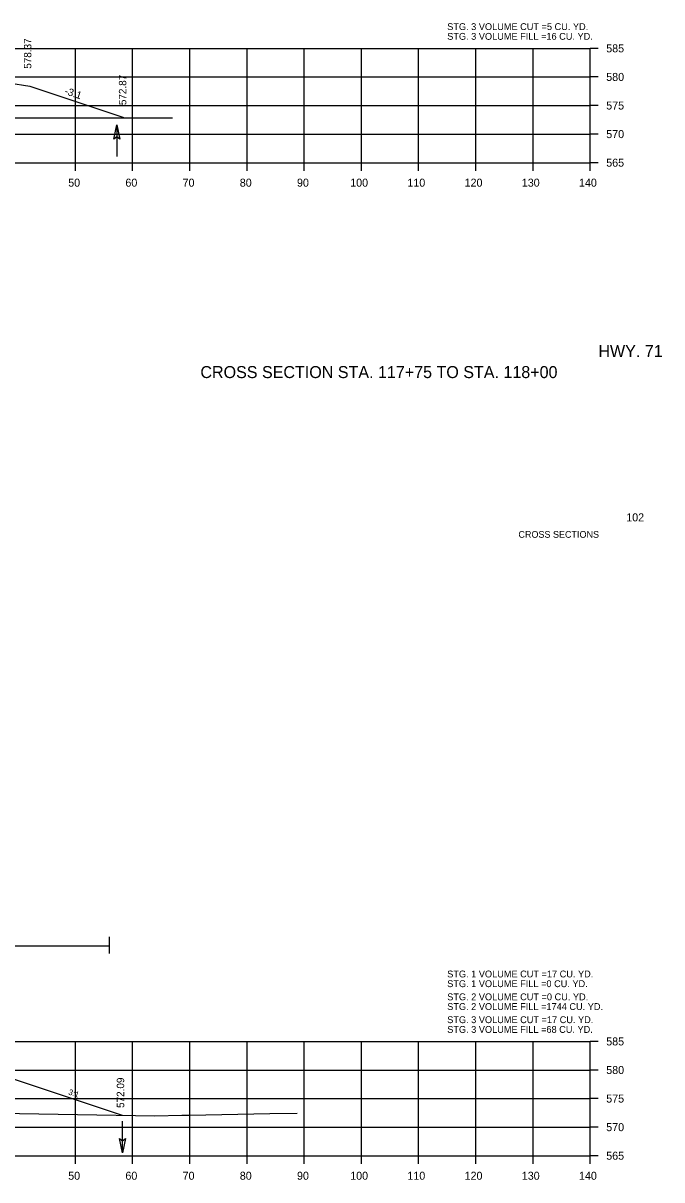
# Model space of a CAD drawing. Extents: x 642114 to 642416, y 286928 to 293347.
# Drawn here: x 642301.1 to 642412.8, y 290342.3 to 290544.7 of the extents above; entities that cross this region are included whole.
import ezdxf

# ---------------------------------------------------------------- set-up
doc = ezdxf.new("R2010")
doc.units = 0
for name, color, linetype in [('Level 43', 7, 'Continuous'), ('Level 58', 7, 'Continuous'), ('R_Axis', 7, 'Continuous'), ('R_Axis Annot', 7, 'Continuous'), ('R_Border', 7, 'Continuous'), ('R_Border Notes', 7, 'Continuous'), ('R_Draft', 7, 'Continuous'), ('R_Exist Surface Annot', 7, 'Continuous'), ('R_Fin Surface', 7, 'Continuous'), ('R_Grid', 7, 'Continuous'), ('R_Xsect Elev', 7, 'Continuous'), ('R_Xsect Slope', 7, 'Continuous')]:
    doc.layers.add(name, color=color, linetype=linetype)

# ---------------------------------------------------------------- blocks, each defined once
blk = doc.blocks.new('FA')
at = {"layer": 'Level 43'}
blk.add_lwpolyline([(7.94, 0), (0, 0)], dxfattribs=at)
at = {"layer": 'Level 58'}
blk.add_lwpolyline([(4.34, 0.75), (7.94, 0), (4.34, -0.75), (4.94, 0)], close=True, dxfattribs=at)

msp = doc.modelspace()

# ---------------------------------------------------------------- linework, layer by layer
at = {"layer": 'R_Axis'}
for p, q in [((642400.24, 290520.27), (642400.24, 290540.27)), ((642401.64, 290540.27), (642400.24, 290540.27)), ((642401.64, 290535.27), (642400.24, 290535.27)), ((642401.64, 290530.27), (642400.24, 290530.27)), ((642401.64, 290525.27), (642400.24, 290525.27)), ((642120.24, 290520.27), (642400.24, 290520.27)), ((642310.24, 290518.87), (642310.24, 290520.27)), ((642320.24, 290518.87), (642320.24, 290520.27)), ((642330.24, 290518.87), (642330.24, 290520.27)), ((642340.24, 290518.87), (642340.24, 290520.27)), ((642350.24, 290518.87), (642350.24, 290520.27)), ((642360.24, 290518.87), (642360.24, 290520.27)), ((642370.24, 290518.87), (642370.24, 290520.27)), ((642380.24, 290518.87), (642380.24, 290520.27)), ((642390.24, 290518.87), (642390.24, 290520.27)), ((642400.24, 290518.87), (642400.24, 290520.27)), ((642401.64, 290520.27), (642400.24, 290520.27)), ((642400.24, 290346.52), (642400.24, 290366.52)), ((642401.64, 290366.52), (642400.24, 290366.52)), ((642401.64, 290361.52), (642400.24, 290361.52)), ((642401.64, 290356.52), (642400.24, 290356.52)), ((642401.64, 290351.52), (642400.24, 290351.52)), ((642120.24, 290346.52), (642400.24, 290346.52)), ((642310.24, 290345.12), (642310.24, 290346.52)), ((642320.24, 290345.12), (642320.24, 290346.52)), ((642330.24, 290345.12), (642330.24, 290346.52)), ((642340.24, 290345.12), (642340.24, 290346.52)), ((642350.24, 290345.12), (642350.24, 290346.52)), ((642360.24, 290345.12), (642360.24, 290346.52)), ((642370.24, 290345.12), (642370.24, 290346.52)), ((642380.24, 290345.12), (642380.24, 290346.52)), ((642390.24, 290345.12), (642390.24, 290346.52)), ((642400.24, 290345.12), (642400.24, 290346.52)), ((642401.64, 290346.52), (642400.24, 290346.52))]:
    msp.add_line(p, q, dxfattribs=at)
at = {"layer": 'R_Exist Surface Annot'}
for points in [[(642120.24, 290526.73), (642133.9, 290526.12), (642151.42, 290525.27), (642164.92, 290525.91), (642175.91, 290526.39), (642186.43, 290529.29), (642196.24, 290531.88), (642200.91, 290532.2), (642201.82, 290532.26), (642203.77, 290532.32), (642213.12, 290532.59), (642214.53, 290532.57), (642224.79, 290532.38), (642225.4, 290532.36), (642231.8, 290532.08), (642245.17, 290527.52), (642248.8, 290526.33), (642256.49, 290525.68), (642271.26, 290524.45), (642288.09, 290527.93), (642289.12, 290528.14), (642290.6, 290528.14), (642327.19, 290528.14)], [(642293.65, 290354.04), (642324.15, 290353.51), (642328.84, 290353.62), (642330.26, 290353.63), (642344.24, 290353.91), (642349.02, 290353.94)]]:
    msp.add_lwpolyline(points, dxfattribs=at)
at = {"layer": 'R_Fin Surface'}
for points in [[(642216.82, 290532.53), (642224.02, 290533.73), (642224.05, 290533.73), (642231.71, 290535.01), (642231.73, 290535.01), (642246.24, 290535.6), (642260.24, 290535.88), (642274.24, 290536.16), (642285.76, 290536.39), (642298.56, 290534.25), (642298.59, 290534.25), (642302.26, 290533.64), (642318.52, 290528.22), (642318.76, 290528.14)], [(642219.45, 290358.77), (642228.47, 290361.77), (642231.77, 290362.87), (642232.18, 290363.01), (642244.99, 290363.52), (642260.24, 290363.82), (642275.49, 290364.13), (642286.18, 290364.34), (642318.41, 290353.61)]]:
    msp.add_lwpolyline(points, dxfattribs=at)
at = {"layer": 'R_Grid'}
for p, q in [((642120.24, 290540.27), (642400.24, 290540.27)), ((642310.24, 290520.27), (642310.24, 290540.27)), ((642320.24, 290520.27), (642320.24, 290540.27)), ((642330.24, 290520.27), (642330.24, 290540.27)), ((642340.24, 290520.27), (642340.24, 290540.27)), ((642350.24, 290520.27), (642350.24, 290540.27)), ((642360.24, 290520.27), (642360.24, 290540.27)), ((642370.24, 290520.27), (642370.24, 290540.27)), ((642380.24, 290520.27), (642380.24, 290540.27)), ((642390.24, 290520.27), (642390.24, 290540.27)), ((642400.24, 290520.27), (642400.24, 290540.27)), ((642120.24, 290535.27), (642400.24, 290535.27)), ((642120.24, 290530.27), (642400.24, 290530.27)), ((642120.24, 290525.27), (642400.24, 290525.27)), ((642120.24, 290520.27), (642400.24, 290520.27)), ((642120.24, 290366.52), (642400.24, 290366.52)), ((642310.24, 290346.52), (642310.24, 290366.52)), ((642320.24, 290346.52), (642320.24, 290366.52)), ((642330.24, 290346.52), (642330.24, 290366.52)), ((642340.24, 290346.52), (642340.24, 290366.52)), ((642350.24, 290346.52), (642350.24, 290366.52)), ((642360.24, 290346.52), (642360.24, 290366.52)), ((642370.24, 290346.52), (642370.24, 290366.52)), ((642380.24, 290346.52), (642380.24, 290366.52)), ((642390.24, 290346.52), (642390.24, 290366.52)), ((642400.24, 290346.52), (642400.24, 290366.52)), ((642120.24, 290361.52), (642400.24, 290361.52)), ((642120.24, 290356.52), (642400.24, 290356.52)), ((642120.24, 290351.52), (642400.24, 290351.52)), ((642120.24, 290346.52), (642400.24, 290346.52))]:
    msp.add_line(p, q, dxfattribs=at)
at = {"layer": 'R_Xsect Elev'}
for p, q in [((642316.22, 290381.91), (642316.22, 290384.83)), ((642230.24, 290383.24), (642316.22, 290383.24))]:
    msp.add_line(p, q, dxfattribs=at)

# ---------------------------------------------------------------- block references
at = {"layer": 'R_Xsect Elev', "xscale": 0.7, "yscale": 0.7}
for p, rotation in [((642317.5, 290521.35), 89.99999999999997), ((642318.49, 290352.57), -90.00000000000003)]:
    msp.add_blockref('FA', p, dxfattribs=dict(at, rotation=rotation))

# ---------------------------------------------------------------- texts
at = {"layer": 'R_Axis Annot'}
for s, height, p in [('585', 1.4, (642403.04, 290539.57)), ('580', 1.4, (642403.04, 290534.57)), ('575', 1.4, (642403.04, 290529.57)), ('570', 1.4, (642403.04, 290524.57)), ('565', 1.4, (642403.04, 290519.57)), ('50', 1.4, (642308.98, 290516.07)), ('60', 1.4, (642318.98, 290516.07)), ('70', 1.4, (642328.98, 290516.07)), ('80', 1.4, (642338.98, 290516.07)), ('90', 1.4, (642348.98, 290516.07)), ('100', 1.4, (642358.28, 290516.07)), ('110', 1.4, (642368.28, 290516.07)), ('120', 1.4, (642378.28, 290516.07)), ('130', 1.4, (642388.28, 290516.07)), ('140', 1.4, (642398.28, 290516.07)), ('HWY. 71', 2.1, (642401.67, 290486.25)), ('CROSS SECTION STA. 117+75 TO STA. 118+00', 2.1, (642332.09, 290482.58)), ('585', 1.4, (642403.04, 290365.82)), ('580', 1.4, (642403.04, 290360.82)), ('575', 1.4, (642403.04, 290355.82)), ('570', 1.4, (642403.04, 290350.82)), ('565', 1.4, (642403.04, 290345.82)), ('50', 1.4, (642308.98, 290342.32)), ('60', 1.4, (642318.98, 290342.32)), ('70', 1.4, (642328.98, 290342.32)), ('80', 1.4, (642338.98, 290342.32)), ('90', 1.4, (642348.98, 290342.32)), ('100', 1.4, (642358.28, 290342.32)), ('110', 1.4, (642368.28, 290342.32)), ('120', 1.4, (642378.28, 290342.32)), ('130', 1.4, (642388.28, 290342.32)), ('140', 1.4, (642398.28, 290342.32))]:
    msp.add_text(s, height=height, dxfattribs=at).set_placement(p)
at = {"layer": 'R_Border'}
msp.add_text('102', height=1.4, dxfattribs=at).set_placement((642406.54, 290457.51))
at = {"layer": 'R_Border Notes'}
msp.add_text('    CROSS SECTIONS    ', height=1.178, dxfattribs=at).set_placement((642385.94, 290454.64))
at = {"layer": 'R_Draft'}
for s, p in [('STG. 3 VOLUME CUT =5 CU. YD.', (642375.24, 290543.47)), ('STG. 3 VOLUME FILL =16 CU. YD.', (642375.24, 290541.77)), ('STG. 1 VOLUME CUT =17 CU. YD.', (642375.24, 290377.72)), ('STG. 1 VOLUME FILL =0 CU. YD.', (642375.24, 290376.02)), ('STG. 2 VOLUME CUT =0 CU. YD.', (642375.24, 290373.72)), ('STG. 2 VOLUME FILL =1744 CU. YD.', (642375.24, 290372.02)), ('STG. 3 VOLUME CUT =17 CU. YD.', (642375.24, 290369.72)), ('STG. 3 VOLUME FILL =68 CU. YD.', (642375.24, 290368.02))]:
    msp.add_text(s, height=1.2, dxfattribs=at).set_placement(p)
at = {"layer": 'R_Xsect Elev'}
for s, p in [(' 578.37', (642302.54, 290536.22)), (' 572.87', (642319.14, 290529.85)), (' 572.09', (642318.77, 290354.4))]:
    msp.add_text(s, height=1.3, rotation=90, dxfattribs=at).set_placement(p)
at = {"layer": 'R_Xsect Slope'}
for s, height, rotation, p in [('-3:1', 1.3, 341.5691, (642308.25, 290532.29)), ('3:1', 1, 341.579, (642308.93, 290357.26))]:
    msp.add_text(s, height=height, rotation=rotation, dxfattribs=at).set_placement(p)

doc.saveas('drawing.dxf')
